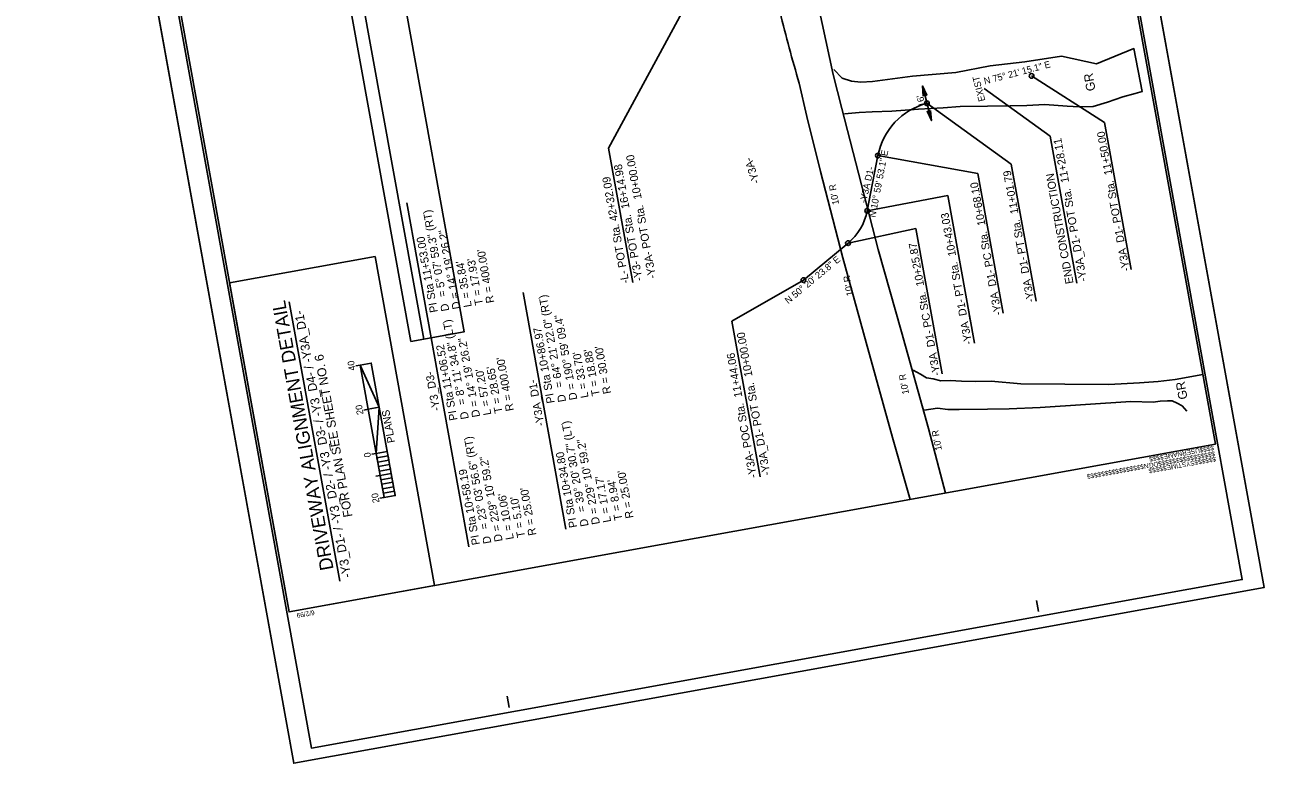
# Model space of a CAD drawing. Extents: x 1620652 to 1621205, y 897765 to 898506.
# Drawn here: x 1620652 to 1621205, y 897765 to 898094 of the extents above; entities that cross this region are included whole.
import ezdxf

# ---------------------------------------------------------------- set-up
doc = ezdxf.new("R2010")
doc.units = 0
for name, color, linetype in [('Default', 7, 'Continuous'), ('Exist Roads EOP', 7, 'Continuous'), ('Exist Roads Soil', 7, 'Continuous'), ('Exist Roads Soil Text', 7, 'Continuous'), ('Prop Dimension', 7, 'Continuous'), ('Prop Horizontal Alignment', 7, 'Continuous'), ('Prop Horizontal Alignment Curve and Spiral Data', 7, 'Continuous'), ('Prop Horizontal Alignment Direction Label', 7, 'Continuous'), ('Prop Horizontal Alignment Station Label', 7, 'Continuous'), ('Prop Terminator CELL', 7, 'Continuous'), ('Sheet Block Revision CELL', 7, 'Continuous'), ('Sheet Cutting Line CELL', 7, 'Continuous'), ('Sheet Data Field CELL', 7, 'Continuous'), ('Sheet Layout Plan Border', 7, 'Continuous'), ('Sheet Plan CELL', 7, 'Continuous'), ('Sheet Plot Border Inside CELL', 7, 'Continuous'), ('Sheet Plot Border Outside CELL', 7, 'Continuous'), ('Sheet Title CELL', 7, 'Continuous'), ('Sheet Typical CELL', 7, 'Continuous')]:
    doc.layers.add(name, color=color, linetype=linetype)

msp = doc.modelspace()

# ---------------------------------------------------------------- linework, layer by layer
at = {"layer": 'Default'}
msp.add_line((1620792.28, 897845.97), (1620769.74, 897970.52), dxfattribs=at)
msp.add_lwpolyline([(1620769.66, 897832.27), (1620834.58, 897844.02), (1620808.02, 897990.75), (1620743.1, 897979)], close=True, dxfattribs=at)
at = {"layer": 'Exist Roads EOP'}
for points in [[(1621005.9, 898102.25), (1621012.34, 898072.02), (1621016.26, 898056.83), (1621022.54, 898032.5), (1621032.42, 897993.85), (1621042.89, 897957.22), (1621054.85, 897914), (1621062.57, 897885.28)], [(1620997.22, 898068.12), (1621000.59, 898053.21), (1621006.73, 898028.68), (1621016.65, 897990.19), (1621027.05, 897952.44), (1621038.8, 897909.99), (1621046.66, 897882.4)]]:
    msp.add_lwpolyline(points, dxfattribs=at)
msp.add_spline([(1620950, 898247.15), (1620955.45, 898230.24), (1620962.17, 898202.75), (1620969.53, 898177.07), (1620975.83, 898152.51), (1620982.98, 898125.57), (1620988.73, 898099.66), (1620997.22, 898068.12)], degree=3, dxfattribs=at)
at = {"layer": 'Exist Roads Soil'}
for points in [[(1621017.37, 898054.35), (1621023.92, 898055.05), (1621029.77, 898055.32), (1621038.5, 898055.56), (1621050.39, 898056.56), (1621061.51, 898057.13), (1621069, 898057.71), (1621081.24, 898057.9), (1621091.3, 898057.95), (1621098.76, 898058.17), (1621106.82, 898058.55), (1621116.74, 898057.76), (1621122.06, 898057.49), (1621128.35, 898057.71), (1621134.82, 898059.57), (1621141.62, 898061.93), (1621147.08, 898063.54), (1621150.24, 898064.42), (1621146.57, 898083.54), (1621129.87, 898076.68), (1621114.28, 898080.08), (1621097.92, 898077.53), (1621082.47, 898075.88), (1621067.16, 898072.87), (1621047.78, 898071.17), (1621029.88, 898068.79), (1621024.76, 898068.46), (1621020.5, 898068.92), (1621016.43, 898070.34), (1621012.65, 898074.24)], [(1621048.04, 897940.01), (1621051.38, 897938.25), (1621054.07, 897936.69), (1621057.06, 897936.21), (1621060.44, 897935.29), (1621064.53, 897935.45), (1621069.64, 897935.14), (1621076.07, 897934.98), (1621082.93, 897935.11), (1621096.06, 897933.99), (1621135.38, 897933.69), (1621149.06, 897934.4), (1621157.44, 897935.05), (1621164.96, 897935.98), (1621177.33, 897938.1)], [(1621170.18, 897921.83), (1621168.04, 897924.18), (1621165.85, 897925.36), (1621163.55, 897926.37), (1621161.59, 897926.46), (1621158.23, 897926.27), (1621155.08, 897925.77), (1621145.13, 897926.1), (1621104.68, 897923.43), (1621090.95, 897922.78), (1621081.29, 897922.64), (1621068.59, 897922.46), (1621063.58, 897922.54), (1621058.96, 897923.08), (1621052.99, 897922.28)]]:
    msp.add_lwpolyline(points, dxfattribs=at)
at = {"layer": 'Prop Dimension'}
msp.add_line((1621052.21, 898066.85), (1621056.25, 898051.37), dxfattribs=at)
at = {"layer": 'Prop Horizontal Alignment'}
for p, q in [((1621027.59, 898011.21), (1621032.37, 898035.81)), ((1620999.09, 897980.22), (1621019, 897996.73))]:
    msp.add_line(p, q, dxfattribs=at)
for centre, radius, start, end in [((1621061.82, 898030.09), 30, 104.6458, 169.0019), ((1621061.82, 898030.09), 30, 104.6458, 169.0019), ((1621003.05, 898015.97), 25, 309.6601, 349.0019), ((1621003.05, 898015.97), 25, 309.6601, 349.0019), ((1621003.05, 898015.97), 25, 309.6601, 349.0019)]:
    msp.add_arc(centre, radius, start, end, dxfattribs=at)
at = {"layer": 'Prop Horizontal Alignment Curve and Spiral Data'}
for p, q in [((1620849.87, 897861.34), (1620822.11, 898014.69)), ((1620893.16, 897869.18), (1620874.06, 897974.74))]:
    msp.add_line(p, q, dxfattribs=at)
at = {"layer": 'Prop Horizontal Alignment Station Label'}
for p, q in [((1620912.22, 898039.04), (1620954.2, 898116.85)), ((1621133.43, 898050.56), (1621100.87, 898071.3)), ((1621109.19, 898044.42), (1621079.69, 898065.76)), ((1621054.23, 898059.11), (1621091.84, 898031.89)), ((1621133.43, 898050.56), (1621145.3, 897985.03)), ((1620912.22, 898039.04), (1620923.04, 897979.24)), ((1621109.19, 898044.42), (1621121.05, 897978.91)), ((1621032.37, 898035.81), (1621076.9, 898027.75)), ((1621091.84, 898031.89), (1621102.9, 897970.8)), ((1621076.9, 898027.75), (1621088.17, 897965.48)), ((1621027.59, 898011.21), (1621063.48, 898017.98)), ((1621063.48, 898017.98), (1621075.39, 897952.17)), ((1621019, 897996.73), (1621049.22, 898003.28)), ((1621049.22, 898003.28), (1621060.96, 897938.42)), ((1620967.24, 897961.9), (1620999.09, 897980.22)), ((1620967.24, 897961.9), (1620979.82, 897892.43))]:
    msp.add_line(p, q, dxfattribs=at)
for centre in [(1621100.87, 898071.3), (1621054.23, 898059.11), (1621032.37, 898035.81), (1621027.59, 898011.21), (1621019, 897996.73), (1620999.09, 897980.22)]:
    msp.add_circle(centre, 1.05, dxfattribs=at)
at = {"layer": 'Prop Terminator CELL'}
for points in [[(1621052.6, 898062.3), (1621052.21, 898066.85), (1621054.13, 898062.67), (1621053.21, 898063.03)], [(1621055.87, 898055.92), (1621056.25, 898051.37), (1621054.34, 898055.55), (1621055.26, 898055.19)]]:
    msp.add_lwpolyline(points, close=True, dxfattribs=at)
at = {"layer": 'Sheet Block Revision CELL'}
msp.add_line((1620829.72, 897953.94), (1620773.38, 898265.13), dxfattribs=at)
msp.add_lwpolyline([(1620823.99, 897952.89), (1620767.66, 898264.09), (1620791.49, 898268.42), (1620847.82, 897957.21)], close=True, dxfattribs=at)
at = {"layer": 'Sheet Cutting Line CELL'}
for p, q in [((1621204.68, 897843.14), (1621084.7, 898505.97)), ((1620651.74, 898427.6), (1620771.72, 897764.77)), ((1620771.72, 897764.77), (1621204.68, 897843.14))]:
    msp.add_line(p, q, dxfattribs=at)
at = {"layer": 'Sheet Data Field CELL'}
msp.add_line((1620804.93, 897922.64), (1620802.97, 897922.29), dxfattribs=at)
at = {"layer": 'Sheet Layout Plan Border'}
msp.add_lwpolyline([(1621182.95, 897907.07), (1621076.08, 898497.49), (1620740.08, 898436.67), (1620754.33, 898357.93), (1620677.04, 898343.94), (1620769.66, 897832.26)], close=True, dxfattribs=at)
at = {"layer": 'Sheet Plan CELL'}
msp.add_line((1620769.66, 897832.27), (1620769.66, 897832.27), dxfattribs=at)
at = {"layer": 'Sheet Plot Border Inside CELL'}
msp.add_lwpolyline([(1620660.9, 898427.42), (1620779.63, 897771.48), (1621194.92, 897846.65), (1621076.19, 898502.6)], close=True, dxfattribs=at)
at = {"layer": 'Sheet Plot Border Outside CELL'}
msp.add_lwpolyline([(1620651.74, 898427.6), (1620771.72, 897764.77), (1621204.68, 897843.14), (1621084.7, 898505.97)], close=True, dxfattribs=at)
at = {"layer": 'Sheet Title CELL'}
for p, q in [((1620801.38, 897942.32), (1620799.41, 897941.96)), ((1620801.38, 897942.32), (1620812.06, 897883.28)), ((1620816.98, 897884.17), (1620806.3, 897943.21)), ((1620804.94, 897922.64), (1620809.86, 897923.53)), ((1620804.94, 897922.64), (1620802.98, 897922.28)), ((1620808.51, 897902.96), (1620806.54, 897902.6)), ((1620810.29, 897893.12), (1620808.31, 897892.76)), ((1620812.06, 897883.28), (1620810.1, 897882.92))]:
    msp.add_line(p, q, dxfattribs=at)
for points in [[(1620801.38, 897942.32), (1620809.86, 897923.53), (1620806.3, 897943.21)], [(1620808.51, 897902.96), (1620809.86, 897923.53), (1620813.43, 897903.85)], [(1620809.21, 897899.02), (1620808.86, 897900.99), (1620813.78, 897901.88), (1620814.13, 897899.91)], [(1620809.93, 897895.09), (1620809.57, 897897.05), (1620814.49, 897897.94), (1620814.85, 897895.98)], [(1620810.64, 897891.15), (1620810.29, 897893.12), (1620815.2, 897894.01), (1620815.56, 897892.04)], [(1620811.35, 897887.21), (1620811, 897889.18), (1620815.92, 897890.07), (1620816.28, 897888.11)], [(1620812.06, 897883.28), (1620811.71, 897885.24), (1620816.63, 897886.14), (1620816.98, 897884.17)]]:
    msp.add_lwpolyline(points, close=True, dxfattribs=at)
at = {"layer": 'Sheet Typical CELL'}
for p, q in [((1621182.94, 897907.09), (1621182.94, 897907.09)), ((1621182.94, 897907.09), (1621182.94, 897907.09)), ((1621182.94, 897907.09), (1621182.94, 897907.09)), ((1621182.94, 897907.09), (1621182.94, 897907.09)), ((1621182.94, 897907.09), (1621182.94, 897907.09)), ((1621182.94, 897907.09), (1621182.94, 897907.09)), ((1621103.98, 897832.43), (1621103.09, 897837.35)), ((1620867.82, 897789.68), (1620866.93, 897794.6))]:
    msp.add_line(p, q, dxfattribs=at)
msp.add_lwpolyline([(1620662.79, 898422.69), (1620769.66, 897832.28), (1621182.94, 897907.09), (1621076.08, 898497.49)], close=True, dxfattribs=at)
msp.add_lwpolyline([(1621180.27, 897921.85), (1621180.27, 897921.85)], dxfattribs=at)

# ---------------------------------------------------------------- texts
at = {"layer": 'Default'}
for s, height, p in [('DRIVEWAY ALIGNMENT DETAIL', 6, (1620789.55, 897851.34)), ('-Y3_D1- / -Y3_D2- / -Y3_D3- / -Y3_D4- / -Y3A_D1-', 4, (1620797.38, 897847.9)), ('FOR PLAN SEE SHEET NO. 6', 4, (1620797.95, 897874.88))]:
    msp.add_text(s, height=height, rotation=100.2599, dxfattribs=at).set_placement(p)
at = {"layer": 'Exist Roads Soil Text'}
for p in [(1621129.46, 898064.92), (1621170.53, 897927.4)]:
    msp.add_text('GR', height=4, rotation=100.2583, dxfattribs=at).set_placement(p)
at = {"layer": 'Prop Dimension'}
for s, rotation, p in [('EXIST', 104.6458, (1621080.3, 898060.33)), ("16'", 104.6458, (1621053.67, 898057.96)), ("10' R", 100.2599, (1621015.03, 898014.14)), ("10' R", 100.2599, (1621021.42, 897973.42)), ("10' R", 100.2599, (1621046.23, 897929.56)), ("10' R", 100.2599, (1621060.9, 897904.51))]:
    msp.add_text(s, height=3, rotation=rotation, dxfattribs=at).set_placement(p)
at = {"layer": 'Prop Horizontal Alignment Curve and Spiral Data'}
for s, p in [('= 5%%d 07\' 59.3" (RT)', (1620839.84, 897973.08)), ('D = 14%%d 19\' 26.2"', (1620846.17, 897967.57)), ('PI Sta 11+53.00', (1620836.07, 897966.09)), ("T = 17.93'", (1620856.21, 897969.39)), ("R = 400.00'", (1620861.22, 897970.3)), ("L = 35.84'", (1620851.19, 897968.48)), ('= 64%%d 21\' 22.0" (RT)', (1620891.95, 897932.58)), ('D', (1620841.15, 897966.66)), ('= 8%%d 11\' 34.8" (LT)', (1620848.56, 897924.91)), ('D = 190%%d 59\' 09.4"', (1620898.28, 897927.07)), ('PI Sta 10+86.97', (1620888.18, 897925.59)), ('PI Sta 11+06.52', (1620844.79, 897917.92)), ('D = 14%%d 19\' 26.2"', (1620854.89, 897919.4)), ("R = 30.00'", (1620913.34, 897929.8)), ("R = 400.00'", (1620869.94, 897922.12)), ("L = 33.70'", (1620903.3, 897927.98)), ("T = 18.88'", (1620908.32, 897928.89)), ("L = 57.20'", (1620859.91, 897920.3)), ("T = 28.65'", (1620864.93, 897921.21)), ('-Y3_D3-', (1620837.05, 897922.21)), ('-Y3A_D1-', (1620883.56, 897915.45)), ('D', (1620893.26, 897926.16)), ('D', (1620849.87, 897918.49)), ('= 39%%d 20\' 30.7" (LT)', (1620901.99, 897877.08)), ('= 23%%d 03\' 56.6" (RT)', (1620858.6, 897869.4)), ('D = 229%%d 10\' 59.2"', (1620908.33, 897871.56)), ('D = 229%%d 10\' 59.2"', (1620864.94, 897863.89)), ('PI Sta 10+34.80', (1620898.23, 897870.09)), ('PI Sta 10+58.19', (1620854.84, 897862.41)), ("L = 17.17'", (1620913.35, 897872.47)), ("T = 8.94'", (1620918.37, 897873.38)), ("R = 25.00'", (1620923.38, 897874.29)), ("L = 10.06'", (1620869.95, 897864.8)), ("R = 25.00'", (1620879.99, 897866.62)), ("T = 5.10'", (1620874.97, 897865.71)), ('D', (1620903.31, 897870.66)), ('D', (1620859.92, 897862.98))]:
    msp.add_text(s, height=3.57, rotation=100.2599, dxfattribs=at).set_placement(p)
at = {"layer": 'Prop Horizontal Alignment Direction Label'}
for s, rotation, p in [('N 75%%d 21\' 15.1" E', 14.6458, (1621080.03, 898067.49)), ('N 10%%d 59\' 53.1" E', 79.0019, (1621031.18, 898007.99)), ('-Y3A D1-', 77.4584, (1621027.09, 898014.41)), ('N 50%%d 20\' 23.8" E', 39.6601, (1620992.34, 897969.47))]:
    msp.add_text(s, height=3, rotation=rotation, dxfattribs=at).set_placement(p)
at = {"layer": 'Prop Horizontal Alignment Station Label'}
for s, height, rotation, p in [('-Y3A_D1- POT Sta.  11+50.00', 3.5, 100.2599, (1621144.71, 897984.49)), ('-Y3A_D1- POT Sta.  11+28.11', 3.584, 100.2599, (1621125.63, 897979.96)), ('-Y3A- POT Sta.  10+00.00', 3.584, 100.2599, (1620933.41, 897981.24)), ('-Y3A-', 3.5, 108.2452, (1620979.67, 898023.89)), ('-Y3- POT Sta.  16+14.98', 3.584, 100.2599, (1620927.42, 897980.16)), ('-Y3A_D1- PT Sta.  11+01.79', 3.5, 100.2599, (1621102.18, 897970.65)), ('-L- POT Sta. 42+32.09', 3.584, 100.2599, (1620921.42, 897979.07)), ('-Y3A_D1- PC Sta.  10+68.10', 3.5, 100.2599, (1621087.59, 897964.9)), ('END CONSTRUCTION', 3.584, 100.2599, (1621119.64, 897978.88)), ('-Y3A_D1- PT Sta.  10+43.03', 3.5, 100.2599, (1621074.38, 897951.77)), ('-Y3A_D1- PC Sta.  10+25.87', 3.5, 100.2599, (1621060.21, 897937.9)), ('-Y3A_D1- POT Sta.  10+00.00', 3.584, 100.2599, (1620984.39, 897893.44)), ('-Y3A- POC Sta.  11+44.06', 3.584, 100.2599, (1620978.39, 897892.35))]:
    msp.add_text(s, height=height, rotation=rotation, dxfattribs=at).set_placement(p)
at = {"layer": 'Sheet Data Field CELL'}
for s, p in [('40', (1620799.33, 897940.14)), ('20', (1620802.89, 897920.46)), ('20', (1620810.02, 897881.1))]:
    msp.add_text(s, height=3, rotation=100.2599, dxfattribs=at).set_placement(p)
at = {"layer": 'Sheet Title CELL'}
for s, height, p in [('PLANS', 3.4, (1620816.95, 897907.94)), ('0', 3, (1620806.28, 897901.44))]:
    msp.add_text(s, height=height, rotation=100.2599, dxfattribs=at).set_placement(p)
at = {"layer": 'Sheet Typical CELL'}
for s, p in [('$$$$USERNAME$$$$', (1621182.09, 897906.5)), ('$$$$$$$$$$$$$$$$DGN$$$$$$$$$$$$$$$$', (1621182.56, 897903.91)), ('$$$$$$SYSTIME$$$$$', (1621182.99, 897901.53)), ('6/2/99', (1620780.81, 897833.02))]:
    msp.add_text(s, height=2.1, rotation=190.2599, dxfattribs=at).set_placement(p)

doc.saveas('drawing.dxf')
